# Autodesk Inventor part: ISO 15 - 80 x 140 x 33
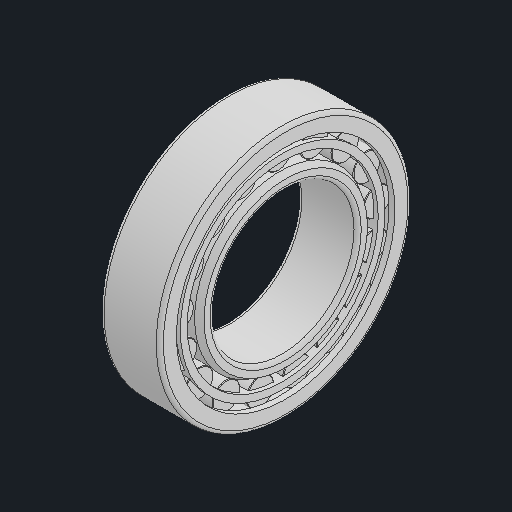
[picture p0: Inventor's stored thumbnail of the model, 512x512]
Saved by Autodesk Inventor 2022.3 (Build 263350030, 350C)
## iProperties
Created: 2020-09
Part Number: ISO 15 - 80 x 140 x 33
Material: Типовые
Document SubType Name: Modeling
Designer: Карташов
Density: 1 g/cm^3
Appearance: По умолчанию
Title: D:\мои документы\Ирина\_WorldSkills\2020_09 ФНЧ\Module A\GIVEN\ISO 15 - 80 x 140 x 33.stp
Author: Дом
Sending System: Autodesk Inventor 2021
Preprocessor: ST-DEVELOPER v18.1
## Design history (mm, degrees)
feature "Твердое тело2"
node "Твердое тело1"
